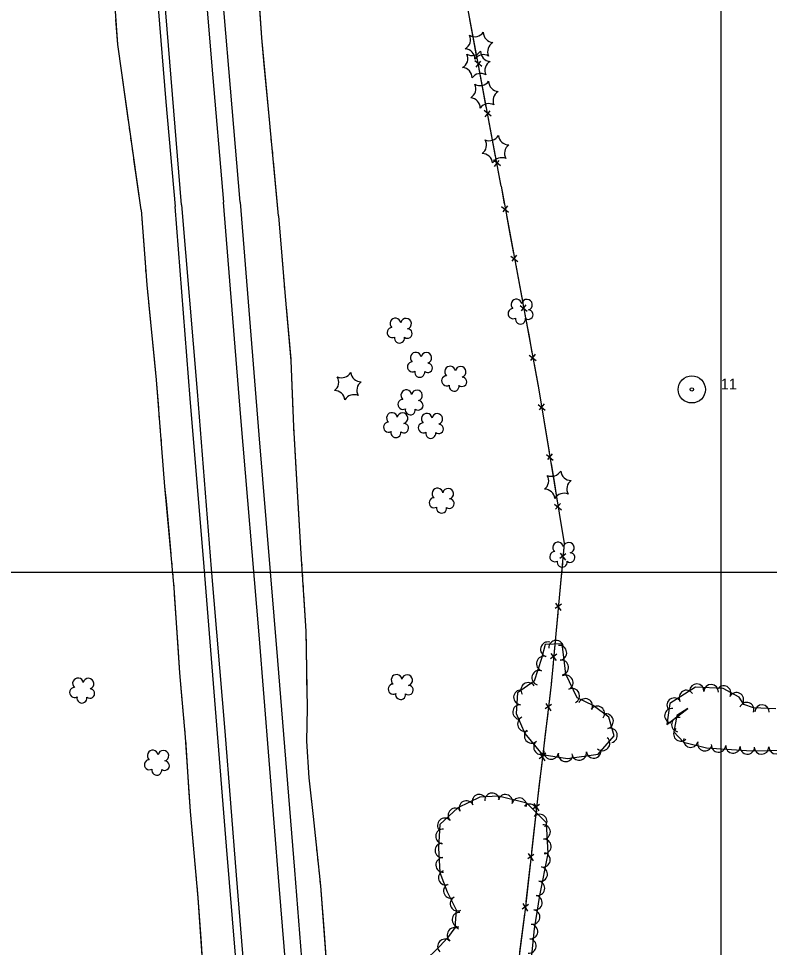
# Model space of a CAD drawing. Extents: x 353423 to 364002, y 127000 to 201942.
# Drawn here: x 361612 to 362027, y 130793 to 131306 of the extents above; entities that cross this region are included whole.
import ezdxf

# ---------------------------------------------------------------- set-up
doc = ezdxf.new("R2010")
doc.units = 0
for name, color, linetype in [('E_DTM_SlopeBottom', 7, 'Continuous'), ('E_DTM_SlopeTop', 7, 'Continuous'), ('E_FEN_Generic', 7, 'Continuous'), ('E_LAND_TreeLine', 7, 'Continuous'), ('E_RDWY_AsphConc', 7, 'Continuous'), ('E_STRUCT_WingWall', 7, 'Continuous')]:
    doc.layers.add(name, color=color, linetype=linetype)

msp = doc.modelspace()

# ---------------------------------------------------------------- linework, layer by layer
at = {"layer": 'E_DTM_SlopeBottom'}
for p, q in [((361867.7, 131279.46), (361863.82, 131282.52)), ((361864.48, 131279.03), (361867.08, 131282.37)), ((361872.83, 131252.03), (361868.95, 131255.09)), ((361869.61, 131251.6), (361872.21, 131254.94)), ((361877.96, 131224.6), (361874.08, 131227.66)), ((361874.74, 131224.17), (361877.34, 131227.51)), ((361878.62, 131202.09), (361882.48, 131199.03)), ((361881.83, 131202.51), (361879.23, 131199.18)), ((361883.72, 131174.71), (361887.58, 131171.64)), ((361886.93, 131175.13), (361884.33, 131171.8)), ((361892.03, 131147.75), (361889.42, 131144.42)), ((361888.81, 131147.32), (361892.68, 131144.26)), ((361893.91, 131119.94), (361897.78, 131116.88)), ((361897.13, 131120.37), (361894.52, 131117.04)), ((361898.84, 131092.57), (361902.64, 131089.43)), ((361902.06, 131092.92), (361899.39, 131089.65)), ((361906.58, 131065.44), (361903.91, 131062.17)), ((361903.36, 131065.08), (361907.16, 131061.94)), ((361907.88, 131037.6), (361911.68, 131034.46)), ((361911.1, 131037.96), (361908.43, 131034.69)), ((361914.22, 131010.04), (361910.81, 131007.55)), ((361911.01, 131010.51), (361913.9, 131006.51)), ((361911.66, 130982.31), (361908.25, 130979.82)), ((361908.45, 130982.78), (361911.34, 130978.78)), ((361909.1, 130954.57), (361905.69, 130952.08)), ((361905.89, 130955.04), (361908.78, 130951.04)), ((361906.23, 130926.83), (361902.75, 130924.43)), ((361903.04, 130927.39), (361905.81, 130923.31)), ((361902.9, 130899.18), (361899.41, 130896.78)), ((361899.7, 130899.74), (361902.47, 130895.66)), ((361899.59, 130871.54), (361896.13, 130869.11)), ((361896.39, 130872.06), (361899.2, 130868.01)), ((361896.52, 130843.85), (361893.06, 130841.43)), ((361893.32, 130844.38), (361896.13, 130840.33)), ((361893.45, 130816.17), (361889.99, 130813.74)), ((361890.28, 130816.73), (361893.02, 130812.63))]:
    msp.add_line(p, q, dxfattribs=at)
for points in [[(361878.29, 131213.33), (361848.45, 131372.9), (361823.99, 131512.17), (361810.41, 131584.23), (361778.23, 131766.92), (361767.39, 131841.96), (361758.28, 131940.75), (361750.91, 132031.6), (361745.14, 132114.91), (361734.25, 132261.02), (361730.83, 132314.1), (361722.15, 132402.74), (361735.2, 132462.79), (361756.62, 132560.57), (361777.4, 132659.3), (361799.83, 132762.09), (361820.91, 132859.48), (361836.68, 132931.42), (361851.79, 133001.8)], [(361862.9, 131295.63), (361861.07, 131305.43)], [(361864.99, 131284.48), (361862.9, 131295.63)], [(361868.03, 131268.19), (361866.2, 131278)], [(361870.12, 131257.05), (361868.03, 131268.19)], [(361873.16, 131240.76), (361871.33, 131250.57)], [(361875.25, 131229.62), (361873.16, 131240.76)], [(361878.29, 131213.33), (361876.46, 131223.14)], [(361878.29, 131213.33), (361899.27, 131100.66), (361913.24, 131015.71), (361906.05, 130937.86), (361898.42, 130874.63), (361891.8, 130814.89), (361881.91, 130738), (361866.46, 130610.19), (361874.59, 130520.63), (361883.58, 130429.17), (361894.43, 130324.49), (361908.79, 130193.64), (361917.83, 130117.01), (361930.34, 130048.28), (361939.3, 129996.68), (362022.57, 129560.44)], [(361878.29, 131213.33), (361880.11, 131203.55)], [(361881.32, 131197.08), (361883.39, 131185.95)], [(361883.39, 131185.95), (361885.21, 131176.16)], [(361886.42, 131169.7), (361888.49, 131158.57)], [(361888.49, 131158.57), (361890.31, 131148.78)], [(361891.52, 131142.31), (361893.59, 131131.19)], [(361893.59, 131131.19), (361895.41, 131121.4)], [(361896.61, 131114.93), (361898.68, 131103.8)], [(361898.68, 131103.8), (361899.27, 131100.66), (361900.37, 131093.99)], [(361901.43, 131087.5), (361903.27, 131076.33)], [(361903.27, 131076.33), (361904.89, 131066.51)], [(361905.95, 131060.02), (361907.79, 131048.85)], [(361907.79, 131048.85), (361909.41, 131039.03)], [(361910.47, 131032.53), (361912.31, 131021.37)], [(361912.31, 131021.37), (361913.24, 131015.71), (361912.85, 131011.51)], [(361912.25, 131004.95), (361911.21, 130993.68)], [(361911.21, 130993.68), (361910.29, 130983.77)], [(361909.69, 130977.22), (361908.65, 130965.95)], [(361908.65, 130965.95), (361907.73, 130956.04)], [(361907.12, 130949.48), (361906.08, 130938.21)], [(361906.08, 130938.21), (361906.05, 130937.86), (361904.9, 130928.33)], [(361904.11, 130921.8), (361902.76, 130910.56)], [(361902.76, 130910.56), (361901.57, 130900.68)], [(361900.78, 130894.15), (361899.42, 130882.91)], [(361899.42, 130882.91), (361898.42, 130874.63), (361898.25, 130873.02)], [(361897.52, 130866.48), (361896.27, 130855.24)], [(361896.27, 130855.24), (361895.17, 130845.34)], [(361894.45, 130838.8), (361893.2, 130827.55)], [(361893.2, 130827.55), (361892.1, 130817.66)], [(361891.31, 130811.13), (361889.87, 130799.9)], [(361889.87, 130799.9), (361888.6, 130790.03)]]:
    msp.add_lwpolyline(points, dxfattribs=at)
at = {"layer": 'E_DTM_SlopeTop'}
for points in [[(361701.71, 131202.96), (361689.46, 131352.21), (361683.54, 131427.34), (361674.54, 131532.78), (361667.21, 131625.02), (361659.98, 131711.44), (361654.85, 131771.26), (361647.7, 131864.55), (361638.67, 131973.24), (361630.68, 132070.93), (361623.51, 132153.46), (361617.17, 132235.74), (361610.5, 132318.65), (361603.31, 132406.03), (361593.97, 132521.61), (361585.27, 132622.71), (361577.32, 132720.55), (361568.39, 132827.48), (361560.9, 132917.02), (361554.51, 132990.77)], [(361551.45, 132989.7), (361560.45, 132880.42), (361570.24, 132767.91), (361577.31, 132679.08), (361583.75, 132595.28), (361591.05, 132509.44), (361600.05, 132398.27), (361606.48, 132319.96), (361611.97, 132249.12), (361619.29, 132161.12), (361626.21, 132076.06), (361632.16, 132001.61), (361638.47, 131926.13), (361646.27, 131832.06), (361653.28, 131745.01), (361660.15, 131662.02), (361669.41, 131549.37), (361677.12, 131450.84), (361684.59, 131364.08), (361693.04, 131260.01), (361698.08, 131202.07)], [(361734.02, 131204.53), (361719.93, 131371.94), (361710.39, 131489.17), (361703.84, 131570.12), (361699.92, 131620.16), (361695.47, 131675.04), (361690.96, 131747.41), (361684.52, 131851.92), (361678.72, 131943.22), (361671.91, 132054.56), (361668.1, 132120.89), (361665.77, 132185.51), (361664.47, 132256.46), (361665.48, 132318.25), (361666.76, 132369.69), (361668.94, 132423.09), (361674.4, 132497.71), (361682.27, 132578.01), (361691.12, 132650.84), (361707.85, 132759.38), (361727.29, 132862.24), (361751.86, 132981.48)], [(361684.79, 131759.79), (361690.59, 131665.49), (361695.04, 131598.79), (361698.8, 131532.24), (361699.75, 131512.38), (361705.19, 131441.4), (361712.2, 131355.21), (361718.44, 131279.62)], [(361718.44, 131279.62), (361724.97, 131204.46)], [(361978.48, 129307.03), (361938.07, 129500.9), (361920.01, 129589.3), (361899.44, 129690.14), (361881.21, 129779.34), (361862.54, 129877.8), (361843.33, 129987.94), (361828.53, 130081.63), (361817.52, 130158.71), (361805.56, 130257.48), (361794.34, 130363.06), (361783.52, 130487.48), (361775.19, 130584.98), (361765.97, 130700.85), (361755.64, 130826.83), (361744.53, 130965.28), (361734.5, 131085.4), (361724.97, 131204.46)], [(361734.02, 131204.53), (361744.47, 131075.92), (361754.78, 130951.04), (361764.16, 130835.27), (361772.34, 130730.19), (361780.74, 130632.05), (361787.65, 130543.66), (361795.79, 130445.01), (361804.28, 130345.72), (361813.81, 130262.96), (361823.3, 130185.29), (361830.22, 130129.6), (361839.96, 130063.62), (361853.52, 129981.74), (361868.3, 129895.14), (361884.41, 129807.54), (361900.64, 129728.29), (361918.01, 129641.67), (361937.34, 129550.79), (361957.21, 129452.35), (361974.28, 129367.89), (361986.96, 129308.18)], [(361951.2, 129303.45), (361929, 129410.45), (361914.16, 129483.88), (361898.79, 129558.31), (361886.21, 129623.21), (361869.75, 129702.92), (361848.14, 129809.21), (361831.67, 129896.38), (361818.56, 129972.87), (361806.25, 130046.79), (361793.34, 130133.84), (361782.36, 130224.24), (361771.17, 130322.5), (361765.11, 130384.99), (361759.23, 130455.9), (361752.3, 130532.28), (361745.85, 130612.97), (361740.22, 130683.54), (361733.24, 130768.13), (361726.51, 130848.42), (361720.51, 130924.54), (361714.18, 131002.94), (361706.55, 131096.01), (361698.08, 131202.07)], [(361701.71, 131202.96), (361710.41, 131099.75), (361718.15, 131001.73), (361725.6, 130912.08), (361731.83, 130832.5), (361740.13, 130729.92), (361747.85, 130638.26), (361755.19, 130548.83), (361763.8, 130450.51), (361773.84, 130337.52), (361783.76, 130245.75), (361795.06, 130153.15), (361806.86, 130072.06), (361818.04, 130001.45), (361830.16, 129930.92), (361844.27, 129852.76), (361857.57, 129783.56), (361872.27, 129708.43), (361889.25, 129627.5), (361902.32, 129562.71), (361920.83, 129470.75), (361933.75, 129405.47), (361954.61, 129303.95)]]:
    msp.add_lwpolyline(points, dxfattribs=at)
at = {"layer": 'E_FEN_Generic'}
for points in [[(361914.22, 130943.54), (361913.42, 130949.8), (361912.04, 130960.42), (361902.78, 130960.05), (361900.64, 130952.26), (361896.64, 130939.72), (361887.35, 130933.22), (361886.71, 130921.75), (361891.5, 130910.72), (361900.96, 130899.23), (361914.98, 130897), (361931.97, 130899.43), (361940.79, 130909.4), (361937.92, 130919.79), (361929.17, 130926.19), (361920.48, 130930.58), (361914.22, 130943.54)], [(362030.21, 130924.46), (362017.88, 130924.87), (362012.57, 130926.72), (362010.04, 130930.92), (362001.12, 130935.67), (361985.79, 130936.32), (361971.69, 130927.41), (361969.88, 130915.7), (361981.58, 130924.61)], [(361981.58, 130924.61), (361975.4, 130920.69), (361973.77, 130911.65), (361979.14, 130905.95), (361991.8, 130902.79), (362016.74, 130901.14), (362038.4, 130901.49)], [(361894.89, 130784.56), (361896.87, 130802.82), (361899.8, 130821.17), (361904.29, 130844.39), (361903.41, 130861.39), (361892.51, 130872.28), (361876.93, 130876.14), (361866.61, 130875.6), (361854.42, 130869.61), (361844.56, 130860.39), (361843.68, 130847.63), (361844.41, 130833.85), (361848.45, 130823.26), (361853.58, 130813.37), (361852.79, 130803.35), (361848.79, 130797.76), (361844.49, 130793.19), (361835.48, 130784.4)]]:
    msp.add_lwpolyline(points, dxfattribs=at)
for centre, radius, start, end in [((361855.73, 131294.25), 5.72, 299.7427, 25.5076), ((361863.78, 131301.66), 5.72, 239.7427, 325.5076), ((361874.22, 131298.39), 5.72, 179.7427, 265.5076), ((361876.61, 131287.72), 5.72, 119.7427, 205.5076), ((361854.22, 131283.82), 5.72, 299.7427, 25.5076), ((361858.12, 131283.58), 5.72, 359.7427, 85.5076), ((361862.27, 131291.23), 5.72, 239.7427, 325.5076), ((361872.71, 131287.97), 5.72, 179.7427, 265.5076), ((361868.56, 131280.31), 5.72, 59.7427, 145.5076), ((361875.1, 131277.29), 5.72, 119.7427, 205.5076), ((361856.61, 131273.15), 5.72, 359.7427, 85.5076), ((361867.05, 131269.88), 5.72, 59.7427, 145.5076), ((361866.74, 131274.59), 5.72, 239.7427, 325.5076), ((361877.18, 131271.32), 5.72, 179.7427, 265.5076), ((361858.69, 131267.18), 5.72, 299.7427, 25.5076), ((361879.58, 131260.65), 5.72, 119.7427, 205.5076), ((361861.08, 131256.5), 5.72, 359.7427, 85.5076), ((361871.52, 131253.24), 5.72, 59.7427, 145.5076), ((361871.86, 131244.15), 5.72, 245.1518, 330.9167), ((361882.56, 131241.88), 5.72, 185.1518, 270.9167), ((361864.54, 131236.02), 5.72, 305.1518, 30.9167), ((361885.95, 131231.48), 5.72, 125.1518, 210.9167), ((361867.93, 131225.61), 5.72, 5.1518, 90.9167), ((361878.63, 131223.34), 5.72, 65.1518, 150.9167), ((361886.81, 131147.87), 2.97, 8.3641, 229.598), ((361892.66, 131147.76), 2.97, 286.0149, 168.9882), ((361884.95, 131142.83), 2.78, 91.335, 299.108), ((361893.42, 131142.29), 2.61, 230.7202, 88.6528), ((361819.95, 131137.4), 2.97, 8.3641, 229.598), ((361825.81, 131137.28), 2.97, 286.0149, 168.9882), ((361889.02, 131139.83), 2.78, 168.012, 9.0231), ((361818.09, 131132.36), 2.78, 91.335, 299.108), ((361826.57, 131131.81), 2.61, 230.7202, 88.6528), ((361822.16, 131129.35), 2.78, 168.012, 9.0231), ((361831.15, 131118.51), 2.97, 8.3641, 229.598), ((361837, 131118.39), 2.97, 286.0149, 168.9882), ((361829.29, 131113.47), 2.78, 91.335, 299.108), ((361837.76, 131112.92), 2.61, 230.7202, 88.6528), ((361850.11, 131110.79), 2.97, 8.3641, 229.598), ((361855.97, 131110.67), 2.97, 286.0149, 168.9882), ((361782.9, 131105.03), 5.72, 305.1518, 30.9167), ((361790.22, 131113.16), 5.72, 245.1518, 330.9167), ((361800.92, 131110.89), 5.72, 185.1518, 270.9167), ((361833.36, 131110.46), 2.78, 168.012, 9.0231), ((361848.25, 131105.75), 2.78, 91.335, 299.108), ((361856.73, 131105.2), 2.61, 230.7202, 88.6528), ((361804.31, 131100.49), 5.72, 125.1518, 210.9167), ((361852.32, 131102.74), 2.78, 168.012, 9.0231), ((361786.29, 131094.62), 5.72, 5.1518, 90.9167), ((361796.99, 131092.35), 5.72, 65.1518, 150.9167), ((361825.96, 131097.73), 2.97, 8.3641, 229.598), ((361831.82, 131097.62), 2.97, 286.0149, 168.9882), ((361824.1, 131092.69), 2.78, 91.335, 299.108), ((361832.58, 131092.15), 2.61, 230.7202, 88.6528), ((361817.99, 131085.16), 2.97, 8.3641, 229.598), ((361823.84, 131085.04), 2.97, 286.0149, 168.9882), ((361828.17, 131089.69), 2.78, 168.012, 9.0231), ((361837.22, 131084.73), 2.97, 8.3641, 229.598), ((361843.07, 131084.62), 2.97, 286.0149, 168.9882), ((361816.12, 131080.12), 2.78, 91.335, 299.108), ((361824.6, 131079.57), 2.61, 230.7202, 88.6528), ((361835.35, 131079.69), 2.78, 91.335, 299.108), ((361843.83, 131079.15), 2.61, 230.7202, 88.6528), ((361820.2, 131077.12), 2.78, 168.012, 9.0231), ((361839.43, 131076.69), 2.78, 168.012, 9.0231), ((361906.29, 131058.65), 5.72, 245.1518, 330.9167), ((361916.99, 131056.38), 5.72, 185.1518, 270.9167), ((361898.97, 131050.51), 5.72, 305.1518, 30.9167), ((361920.38, 131045.97), 5.72, 125.1518, 210.9167), ((361843.22, 131043.39), 2.97, 8.3641, 229.598), ((361849.07, 131043.27), 2.97, 286.0149, 168.9882), ((361902.36, 131040.11), 5.72, 5.1518, 90.9167), ((361841.36, 131038.35), 2.78, 91.335, 299.108), ((361849.83, 131037.8), 2.61, 230.7202, 88.6528), ((361913.06, 131037.84), 5.72, 65.1518, 150.9167), ((361845.43, 131035.34), 2.78, 168.012, 9.0231), ((361909.9, 131013.55), 2.97, 8.3641, 229.598), ((361915.76, 131013.44), 2.97, 286.0149, 168.9882), ((361908.04, 131008.51), 2.78, 91.335, 299.108), ((361916.52, 131007.97), 2.61, 230.7202, 88.6528), ((361912.11, 131005.51), 2.78, 168.012, 9.0231), ((361904.24, 130957.3), 4.08, 74.594, 254.5787), ((361908.76, 130958.15), 4.08, 2.2832, 182.2679), ((361910.54, 130955.4), 4.08, 277.3696, 97.3543), ((361901.96, 130949.38), 4.08, 72.3245, 252.3092), ((361911.58, 130947.31), 4.08, 277.3116, 97.2963), ((361820.57, 130940.36), 2.97, 8.3641, 229.598), ((361826.42, 130940.24), 2.97, 286.0149, 168.9882), ((361899.48, 130941.6), 4.08, 72.3245, 252.3092), ((361914.07, 130938.93), 4.08, 295.7891, 115.7738), ((361644.44, 130938.44), 2.97, 8.3641, 229.598), ((361650.29, 130938.32), 2.97, 286.0149, 168.9882), ((361818.71, 130935.32), 2.78, 91.335, 299.108), ((361827.18, 130934.77), 2.61, 230.7202, 88.6528), ((361893.35, 130934.81), 4.08, 35.0254, 215.01), ((361986.46, 130934.2), 4, 357.5807, 177.5654), ((361994.46, 130933.86), 4, 357.5807, 177.5654), ((362001.39, 130933.16), 4, 331.9315, 151.9162), ((361642.58, 130933.4), 2.78, 91.335, 299.108), ((361651.05, 130932.85), 2.61, 230.7202, 88.6528), ((361822.78, 130932.31), 2.78, 168.012, 9.0231), ((361889.36, 130930.77), 4.08, 86.8032, 266.7879), ((361917.62, 130931.58), 4.08, 295.7891, 115.7738), ((361980.79, 130930.69), 4, 32.3052, 212.2899), ((362008.45, 130929.39), 4, 331.9315, 151.9162), ((361646.65, 130930.4), 2.78, 168.012, 9.0231), ((361924.88, 130925.96), 4.08, 333.2136, 153.1983), ((361974.03, 130926.41), 4, 32.3052, 212.2899), ((362014.15, 130923.95), 4, 340.7589, 160.7436), ((361888.9, 130922.62), 4.08, 86.8032, 266.7879), ((361931.49, 130921.85), 4.08, 323.8265, 143.8112), ((361972.76, 130920.61), 4, 81.227, 261.2116), ((362022.59, 130922.61), 4, 358.1219, 178.1065), ((361891.52, 130916.03), 4.08, 113.4603, 293.4449), ((361936.33, 130917.53), 4.08, 285.4302, 105.4149), ((361976.63, 130915.71), 4, 79.8183, 259.803), ((361895.25, 130909.53), 4.08, 129.4628, 309.4475), ((361938.5, 130909.67), 4.08, 285.4302, 105.4149), ((361977.69, 130910.54), 4, 133.2588, 313.2435), ((361900.43, 130903.23), 4.08, 129.4628, 309.4475), ((361934.36, 130905.35), 4.08, 228.5075, 48.4922), ((361983.2, 130907.09), 4, 166.031, 346.0157), ((361685.77, 130898.56), 2.97, 8.3641, 229.598), ((361691.63, 130898.44), 2.97, 286.0149, 168.9882), ((361905.97, 130900.59), 4.08, 170.9983, 350.983), ((361929.55, 130901.24), 4.08, 188.143, 8.1276), ((361990.96, 130905.16), 4, 166.031, 346.0157), ((361998.54, 130904.44), 4, 176.2104, 356.195), ((362006.52, 130903.91), 4, 176.2104, 356.195), ((362014.51, 130903.38), 4, 176.2104, 356.195), ((362022.33, 130903.32), 4, 180.9251, 0.9098), ((362030.33, 130903.45), 4, 180.9251, 0.9098), ((361683.91, 130893.52), 2.78, 91.335, 299.108), ((361914.03, 130899.32), 4.08, 170.9983, 350.983), ((361921.47, 130900.09), 4.08, 188.143, 8.1276), ((361687.98, 130890.51), 2.78, 168.012, 9.0231), ((361692.39, 130892.97), 2.61, 230.7202, 88.6528), ((361866.3, 130873.11), 4.01, 26.1746, 206.1593), ((361873.35, 130873.85), 4.01, 2.9922, 182.9769), ((361880.62, 130873.06), 4.01, 346.0987, 166.0834), ((361859.11, 130869.57), 4.01, 26.1746, 206.1593), ((361888.39, 130871.14), 4.01, 346.0987, 166.0834), ((361894.06, 130867.76), 4.01, 315.034, 135.0186), ((361853.06, 130865.47), 4.01, 43.0724, 223.0571), ((361899.73, 130862.1), 4.01, 315.034, 135.0186), ((361847.21, 130859.99), 4.01, 43.0724, 223.0571), ((361901.57, 130856.37), 4.01, 272.9861, 92.9708), ((361846.21, 130853.91), 4.01, 86.0657, 266.0504), ((361845.86, 130846.17), 4.01, 93.0656, 273.0503), ((361901.98, 130848.37), 4.01, 272.9861, 92.9708), ((361901.49, 130840.94), 4.01, 259.0632, 79.0479), ((361846.28, 130838.17), 4.01, 93.0656, 273.0503), ((361847.73, 130831.05), 4.01, 110.8772, 290.8619), ((361899.97, 130833.07), 4.01, 259.0632, 79.0479), ((361850.54, 130823.8), 4.01, 117.4054, 297.3901), ((361898.44, 130825.2), 4.01, 259.0632, 79.0479), ((361854.22, 130816.68), 4.01, 117.4054, 297.3901), ((361897.05, 130817.24), 4.01, 260.93, 80.9147), ((361855.25, 130807.85), 4.01, 85.4853, 265.47), ((361895.79, 130809.33), 4.01, 260.93, 80.9147), ((361894.59, 130801.3), 4.01, 263.8111, 83.7958), ((361852.55, 130799.42), 4.01, 54.4098, 234.3945), ((361847.25, 130793.07), 4.01, 46.7582, 226.7429), ((361893.73, 130793.33), 4.01, 263.8111, 83.7958)]:
    msp.add_arc(centre, radius, start, end, dxfattribs=at)
at = {"layer": 'E_LAND_TreeLine'}
for p, q in [((362000, 131000), (362000, 133500)), ((362000, 129000), (362000, 131500)), ((360000, 131000), (363500, 131000)), ((360000, 131000), (364000, 131000))]:
    msp.add_line(p, q, dxfattribs=at)
at = {"layer": 'E_RDWY_AsphConc'}
for radius in [7.5, 7.5, 0.96, 0.96]:
    msp.add_circle((361983.78, 131100.96), radius, dxfattribs=at)
at = {"layer": 'E_STRUCT_WingWall'}
for points in [[(361679.29, 131200.29), (361666.39, 131291.6), (361662.33, 131349.55), (361656.47, 131408.99), (361652.57, 131463.15), (361647.98, 131518.74), (361643.53, 131574.77), (361640.53, 131621.78), (361634.48, 131691), (361628.62, 131752.42), (361622.66, 131809.18), (361619.86, 131844.72), (361617.44, 131888.22), (361616.87, 131897.54)], [(361755.35, 131196.84), (361746.04, 131295.32), (361742.36, 131350.07), (361737.57, 131416.58), (361731.88, 131476.62), (361728.1, 131525.36), (361724.43, 131579.07), (361720.25, 131646.96), (361717.32, 131716.49), (361712.56, 131779.84), (361710.33, 131846.97), (361709.6, 131867.55)], [(361747.44, 131280.51), (361746.04, 131295.32), (361744.99, 131310.88)], [(361668.41, 131277.33), (361666.39, 131291.6), (361665.43, 131305.37)], [(361672.35, 131249.41), (361668.41, 131277.33)], [(361750.31, 131250.18), (361747.44, 131280.51)], [(361673.17, 131243.63), (361672.9, 131245.55)], [(361750.9, 131243.91), (361750.7, 131246)], [(361673.98, 131237.85), (361673.71, 131239.78)], [(361751.49, 131237.63), (361751.29, 131239.72)], [(361674.8, 131232.07), (361674.53, 131234)], [(361752.09, 131231.36), (361751.89, 131233.45)], [(361679.29, 131200.29), (361675.35, 131228.22)], [(361755.35, 131196.84), (361752.48, 131227.17)], [(361679.29, 131200.29), (361682.44, 131158.86), (361687.62, 131106.27), (361692.36, 131047.37), (361697.45, 130991.26), (361700.55, 130944.22), (361703.73, 130908.72), (361706.5, 130867.64), (361710.74, 130819.85), (361713.5, 130779.99)], [(361679.29, 131200.29), (361681.51, 131171.07)], [(361755.35, 131196.84), (361758.93, 131152.26), (361762.16, 131116.93), (361763.58, 131080.21), (361765.83, 131041.64), (361767.69, 131010.05), (361770.43, 130967.28), (361771.11, 130924.84), (361770.77, 130906.57), (361771.98, 130886.32), (361774.4, 130864.93), (361778.48, 130826.52), (361782.27, 130777.15)], [(361755.35, 131196.84), (361757.66, 131168.13)], [(361681.82, 131167.04), (361681.97, 131165.03)], [(361757.97, 131164.17), (361758.13, 131162.18)], [(361682.28, 131161), (361682.43, 131158.98)], [(361758.45, 131158.22), (361758.61, 131156.24)], [(361682.82, 131154.96), (361683.02, 131152.95)], [(361683.42, 131148.93), (361686.29, 131119.76)], [(361758.93, 131152.28), (361758.93, 131152.26), (361759.11, 131150.3)], [(361759.47, 131146.35), (361762.09, 131117.65)], [(361686.29, 131119.76), (361687.62, 131106.27), (361688.88, 131090.58)], [(361762.09, 131117.65), (361762.16, 131116.93), (361763.24, 131088.87)], [(361689.2, 131086.55), (361689.37, 131084.53)], [(361763.4, 131084.9), (361763.47, 131082.92)], [(361689.69, 131080.5), (361689.85, 131078.49)], [(361763.65, 131078.95), (361763.77, 131076.96)], [(361690.18, 131074.46), (361690.34, 131072.44)], [(361764, 131073), (361764.11, 131071.01)], [(361690.66, 131068.41), (361692.36, 131047.37), (361693.1, 131039.21)], [(361764.35, 131067.05), (361765.83, 131041.64), (361766.03, 131038.29)], [(361693.1, 131039.21), (361695.75, 131010.02)], [(361766.03, 131038.29), (361767.69, 131010.05), (361767.72, 131009.53)], [(361696.12, 131006), (361696.3, 131003.98)], [(361767.97, 131005.56), (361768.1, 131003.58)], [(361696.66, 130999.96), (361696.85, 130997.95)], [(361768.35, 130999.62), (361768.48, 130997.63)], [(361697.21, 130993.92), (361697.4, 130991.91)], [(361768.74, 130993.67), (361768.86, 130991.68)], [(361697.68, 130987.87), (361699.6, 130958.63)], [(361769.12, 130987.72), (361770.43, 130967.28), (361770.56, 130958.95)], [(361699.6, 130958.63), (361700.55, 130944.22), (361701.88, 130929.42)], [(361770.56, 130958.95), (361771.03, 130930.15)], [(361702.24, 130925.39), (361702.42, 130923.38)], [(361771.09, 130926.18), (361771.11, 130924.84), (361771.1, 130924.19)], [(361702.78, 130919.35), (361702.96, 130917.34)], [(361771.03, 130920.22), (361770.99, 130918.23)], [(361703.32, 130913.32), (361703.5, 130911.3)], [(361770.91, 130914.26), (361770.88, 130912.28)], [(361703.83, 130907.28), (361705.8, 130878.04)], [(361770.8, 130908.31), (361770.77, 130906.57), (361771.98, 130886.32), (361772.74, 130879.58)], [(361705.8, 130878.04), (361706.5, 130867.64), (361708.17, 130848.84)], [(361772.74, 130879.58), (361774.4, 130864.93), (361775.89, 130850.94)], [(361708.53, 130844.81), (361708.71, 130842.8)], [(361776.31, 130846.99), (361776.52, 130845.01)], [(361776.94, 130841.06), (361777.15, 130839.08)], [(361709.06, 130838.77), (361709.24, 130836.76)], [(361777.57, 130835.13), (361777.78, 130833.16)], [(361709.6, 130832.73), (361709.78, 130830.72)], [(361778.2, 130829.21), (361778.48, 130826.52), (361780.48, 130800.49)], [(361710.14, 130826.69), (361710.74, 130819.85), (361712.29, 130797.48)], [(361780.48, 130800.49), (361782.27, 130777.15), (361782.78, 130771.77)], [(361712.29, 130797.48), (361713.5, 130779.99), (361714.24, 130768.24)]]:
    msp.add_lwpolyline(points, dxfattribs=at)

# ---------------------------------------------------------------- texts
at = {"layer": 'E_RDWY_AsphConc'}
msp.add_text('11', height=6, dxfattribs=at).set_placement((361999.78, 131100.96))
msp.add_text('11', height=6, dxfattribs=at).set_placement((361999.78, 131100.96))

doc.saveas('drawing.dxf')
